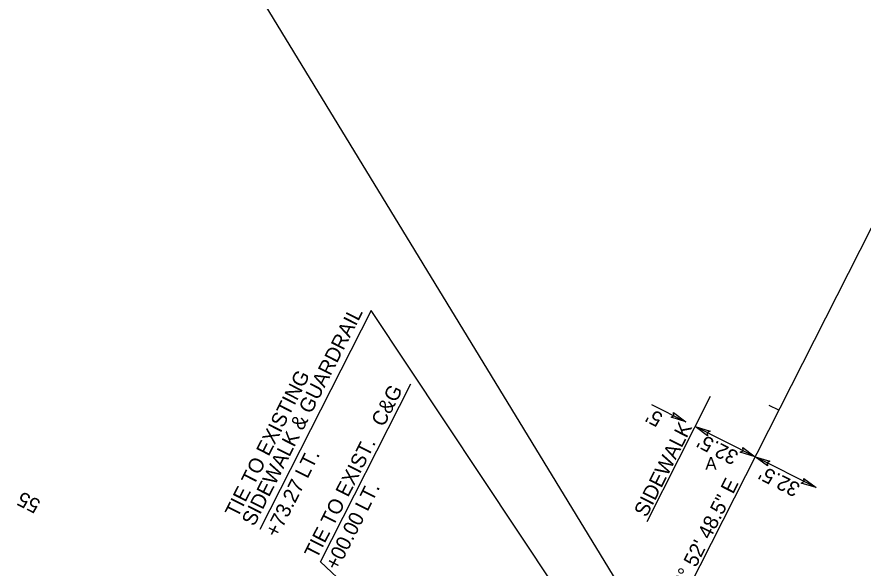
# Model space of a CAD drawing. Extents: x 1974386 to 1979988, y 776712 to 784860.
# Drawn here: x 1977671.3 to 1978072.7, y 782386.9 to 782648.5 of the extents above; entities that cross this region are included whole.
import ezdxf

# ---------------------------------------------------------------- set-up
doc = ezdxf.new("R2010")
doc.units = 0
for name, color, linetype in [('Old_Level_11', 7, 'Continuous'), ('Prop Dimension', 7, 'Continuous'), ('Prop Dimension Text', 7, 'Continuous'), ('Prop DSN Text', 7, 'Continuous'), ('Prop Horizontal Alignment', 7, 'Continuous'), ('Prop Horizontal Alignment Direction Label', 7, 'Continuous'), ('Prop Horizontal Alignment Tick Label', 7, 'Continuous'), ('Prop Horizontal Alignment Tick Small', 7, 'Continuous')]:
    doc.layers.add(name, color=color, linetype=linetype)

msp = doc.modelspace()

# ---------------------------------------------------------------- linework, layer by layer
at = {"layer": 'Old_Level_11'}
msp.add_line((1977975.39, 782348.76), (1977787.3, 782657.18), dxfattribs=at)
for points in [[(1977982.76, 782460.68), (1977988.62, 782456.32), (1977981.59, 782458.45), (1977982.98, 782459.17)], [(1977998.95, 782449.71), (1977993.09, 782454.06), (1978000.12, 782451.94), (1977998.73, 782451.21)], [(1978015.62, 782444.06), (1978021.49, 782439.7), (1978014.45, 782441.83), (1978015.85, 782442.55)], [(1978027.35, 782435.35), (1978021.49, 782439.7), (1978028.53, 782437.58), (1978027.13, 782436.85)], [(1978044.56, 782429.42), (1978050.42, 782425.07), (1978043.38, 782427.19), (1978044.78, 782427.92)]]:
    msp.add_lwpolyline(points, close=True, dxfattribs=at)
at = {"layer": 'Prop Dimension'}
for p, q in [((1977970.29, 782408.98), (1978000.36, 782468.44)), ((1977972.3, 782464.58), (1977988.62, 782456.32)), ((1978021.49, 782439.7), (1977993.09, 782454.06)), ((1978050.42, 782425.07), (1978021.49, 782439.7))]:
    msp.add_line(p, q, dxfattribs=at)
at = {"layer": 'Prop DSN Text'}
for p, q in [((1977839.3, 782509.19), (1977786.5, 782405.24)), ((1977933.68, 782367.22), (1977839.3, 782509.19)), ((1977815.26, 782389.86), (1977858.09, 782474.35)), ((1977913.74, 782297.93), (1977815.26, 782389.86))]:
    msp.add_line(p, q, dxfattribs=at)
at = {"layer": 'Prop Horizontal Alignment'}
msp.add_line((1977839.03, 782079.75), (1978119.82, 782633.69), dxfattribs=at)
at = {"layer": 'Prop Horizontal Alignment Tick Small'}
msp.add_line((1978032.68, 782461.79), (1978028.22, 782464.05), dxfattribs=at)

# ---------------------------------------------------------------- texts
at = {"layer": 'Prop Dimension Text'}
for s, rotation, p in [('SIDEWALK & GUARDRAIL', 63.1199, (1977783.78, 782406.33)), ('TIE TO EXISTING', 63.1199, (1977775.87, 782410.34)), ('TIE TO EXIST.   C&G', 63.1199, (1977813.52, 782390.89)), ("5'", 152.7847, (1977978.29, 782459.74)), ('SIDEWALK', 63.1745, (1977969.92, 782410.61)), ("32.5'", 152.7847, (1978014.16, 782441.72)), ('+73.27 LT.', 63.1199, (1977794.83, 782400.87)), ("32.5'", 152.7847, (1978043.41, 782426.51)), ('+00.00 LT.', 63.1199, (1977823.33, 782385.28))]:
    msp.add_text(s, height=7, rotation=rotation, dxfattribs=at).set_placement(p)
msp.add_text('A', height=6, dxfattribs=at).set_placement((1977997.86, 782433.59))
at = {"layer": 'Prop Horizontal Alignment Direction Label'}
msp.add_text('N 26%%d 52\' 48.5" E', height=7, rotation=63.1199, dxfattribs=at).set_placement((1977981.6, 782363.61))
at = {"layer": 'Prop Horizontal Alignment Tick Label'}
msp.add_text('55', height=7, rotation=153.1199, dxfattribs=at).set_placement((1977683.03, 782418.72))

doc.saveas('drawing.dxf')
